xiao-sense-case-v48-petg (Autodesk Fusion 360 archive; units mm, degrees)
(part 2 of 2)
sketch "Sketch17" plane through (0, 15.93, 0) normal (0, 1, 0) x axis (-1, 0, 0)
  line L1 (6.08, -0.7317) -> (6.08, 1.4923)
  line L2 (6.08, -18.0556) -> (6.08, -15.8317)
  line L3 (11.723, -18.0556) -> (6.08, -18.0556)
  line L4 (17.1014, -8.74) -> (11.723, -18.0556)
  line L5 (17.1014, -7.8234) -> (17.1014, -8.74)
  line L6 (11.723, 1.4923) -> (17.1014, -7.8234)
  line L7 (6.08, 1.4923) -> (11.723, 1.4923)
  line L8 (17.1014, 8.429) -> (17.1014, -7.8234)
  line L9 (-4.8786, -7.7146) -> (-4.8786, 8.429)
  line L10 (6.08, 1.4923) -> (6.08, -0.7317)
  line L11 (0.437, 1.4923) -> (6.08, 1.4923)
  line L12 (-4.8786, -7.7146) -> (0.437, 1.4923)
  line L13 (-4.8786, -8.8487) -> (-4.8786, -7.7146)
  line L14 (0.437, -18.0556) -> (-4.8786, -8.8487)
  line L15 (6.08, -18.0556) -> (0.437, -18.0556)
  line L16 (6.08, -15.8317) -> (6.08, -18.0556)
  line L17 (17.1014, 43.4723) -> (17.1014, 8.429)
  line L18 (-4.8786, 43.4723) -> (17.1014, 43.4723)
  line L19 (-4.8786, 8.429) -> (-4.8786, 43.4723)
  line L20 (17.1014, 1.4923) -> (11.723, 1.4923)
  line L21 (10.58, -7.4067) -> (13.5791, -7.4067)
  line L22 (10.58, -9.1567) -> (10.58, -7.4067)
  line L23 (13.5791, -9.1567) -> (10.58, -9.1567)
  line L24 (1.58, -9.1567) -> (-1.4191, -9.1567)
  line L25 (1.58, -7.4067) -> (1.58, -9.1567)
  line L26 (-1.4191, -7.4067) -> (1.58, -7.4067)
  arc A1 centre (6.08, -8.2817) radius 7.55 clockwise from (6.08, -0.7317) to (13.5791, -7.4067)
  arc A2 centre (6.08, -8.2817) radius 7.55 clockwise from (6.08, -15.8317) to (-1.4191, -9.1567)
  arc A3 centre (6.08, -8.2817) radius 7.55 clockwise from (13.5791, -9.1567) to (6.08, -15.8317)
  arc A4 centre (6.08, -8.2817) radius 7.55 clockwise from (-1.4191, -7.4067) to (6.08, -0.7317)
  point P12 (17.1014, 8.429)
  point P24 (17.1014, 8.429)
  point P13 (-4.8786, 8.429)
  point P27 (-4.8786, 8.429)
  point P10 (11.723, 1.4923)
  point P28 (11.723, 1.4923)
  point P29 (17.1014, 1.4923)
  point P25 (17.1014, 43.4723)
  point P26 (-4.8786, 43.4723)
  coincident P12 P24
  parallel L8 L17
  perpendicular L17 L18
  perpendicular L18 L19
  coincident P13 P27
  coincident P10 P28
  coincident L8 P29
  perpendicular L8 L20
  dimension "d183" distance L7 L18 = 41.98 (= "AntennaLength + d280 - AntennaWidth")
  dimension "d280" distance P25 P26 = 21.98
extrude "Extrude41" add sketch "Sketch17" profile of L6 L8 L20 no distance stored
extrude "Extrude42" add sketch "Sketch17" profile of L7 L8 L9 L11 L12 L17 L18 L19 L20 no distance stored
sketch "Sketch18" plane through (-6.08, 0, 0) normal (1, 0, 0) x axis (0, 1, 0)
  line L1 (13.554, -18.0556) -> (9.88, -14.3817)
  line L2 (9.88, -14.3817) -> (8.5, -14.3817)
  line L3 (8.15, -12.7817) -> (8.15, -14.3817)
  line L4 (8.15, -14.3817) -> (8.5, -14.3817)
  line L5 (8.28, -12.7817) -> (9.88, -14.3817)
  line L6 (8.15, -12.7817) -> (8.28, -12.7817)
  line L7 (8.5, -14.3817) -> (8.5, -12.7817)
  line L8 (8.28, -12.7817) -> (8.5, -12.7817)
  point P4 (8.5, -14.3817)
  point P9 (8.5, -14.3817)
  point P6 (8.15, -14.3817)
  point P10 (8.15, -14.3817)
  point P5 (9.88, -14.3817)
  point P11 (9.88, -14.3817)
  point P8 (8.28, -12.7817)
  point P12 (8.28, -12.7817)
  point P7 (8.15, -12.7817)
  point P13 (8.15, -12.7817)
  point P14 (8.5, -12.7817)
  point P15 (8.5, -12.7817)
  coincident P4 P9
  coincident P6 P10
  coincident P5 P11
  coincident P8 P12
  coincident P7 P13
  coincident P14 P15
extrude "Extrude43" cut sketch "Sketch18" profile of L2 L3 L4 L5 L6 L7 to an object Side2Offset 0
extrude "Extrude44" add sketch "Sketch18" profile of L5 L7 L8 to an object
extrude "Extrude45" add sketch "Sketch18" profile of L5 L7 L8 to an object
sketch "Sketch19" plane through (0, 8.28, 0) normal (0, -1, 0) x axis (1, 0, 0)
  line L1 (-6.08, 0.6923) -> (-6.08, 9.4733)
  line L2 (-2.58, 0.6923) -> (-6.08, 0.6923)
  line L3 (-2.58, -3.7817) -> (-2.58, 0.6923)
  line L4 (-10.57, -3.7817) -> (-2.58, -3.7817)
  line L5 (-10.57, -12.7817) -> (-10.57, -3.7817)
  line L6 (-6.08, -12.7817) -> (-10.57, -12.7817)
  line L7 (-0.5867, -12.7817) -> (-6.08, -12.7817)
  line L8 (0.8736, -12.7817) -> (-0.5867, -12.7817)
  line L9 (3.2786, 6.6413) -> (3.2786, -10.3767)
  line L10 (-6.08, 9.4733) -> (0.2786, 9.4733)
  line L11 (-10.58, -3.7817) -> (-10.58, -12.7817)
  line L12 (-9.58, -3.7817) -> (-10.58, -3.7817)
  line L13 (-9.58, 0.6923) -> (-9.58, -3.7817)
  line L14 (-6.08, 0.6923) -> (-9.58, 0.6923)
  line L15 (-6.08, 9.4733) -> (-6.08, 0.6923)
  line L16 (-12.5014, 9.4733) -> (-6.08, 9.4733)
  line L17 (-15.5014, -10.3767) -> (-15.5014, 6.6413)
  line L18 (-12.2667, -12.7817) -> (-13.0964, -12.7817)
  line L19 (-10.58, -12.7817) -> (-12.2667, -12.7817)
  line L20 (1.4203, 2.8431) -> (-13.5797, 2.8431)
  line L21 (3.2786, 2.8431) -> (1.4203, 2.8431)
  line L22 (-15.5014, 2.8431) -> (-13.5797, 2.8431)
  arc A1 centre (0.8736, -10.3766) radius 2.405 clockwise from (3.2786, -10.3767) to (0.8736, -12.7817)
  closed curve K1 centre (0.2786, 6.6413)
  arc A2 centre (-12.6647, 6.6413) radius 2.8367 clockwise from (-15.5014, 6.6413) to (-12.5014, 9.4733)
  arc A3 centre (-13.0964, -10.3766) radius 2.405 clockwise from (-13.0964, -12.7817) to (-15.5014, -10.3767)
  point P30 (1.4203, 2.8431)
  point P31 (1.4203, 2.8431)
  point P32 (3.2786, 2.8431)
  point P29 (-13.5797, 2.8431)
  point P33 (-13.5797, 2.8431)
  point P34 (-15.5014, 2.8431)
  coincident P30 P31
  coincident L9 P32
  perpendicular L9 L21
  coincident P29 P33
  coincident L17 P34
  perpendicular L17 L22
extrude "Extrude46" add sketch "Sketch19" profile of L1 L15 L16 A2 L17 L20 L22 to an object offset 0.25 (= "Clearance")
extrude "Extrude47" add sketch "Sketch19" profile of L1 L9 K1 L10 L15 L20 L21 to an object offset 0.25 (= "Clearance")
split "Split1"
sketch "Sketch24" plane through (-6.08, 0, 0) normal (-1, 0, 0) x axis (0, -1, 0)
  line L1 (-4.1125, 11.0733) -> (-4.1125, 9.4733)
  line L2 (-9.08, 11.0733) -> (-4.1125, 11.0733)
  line L3 (-9.88, 10.2733) -> (-9.08, 11.0733)
  line L4 (-9.88, 1.4923) -> (-9.88, 10.2733)
  line L5 (-13.58, 1.4923) -> (-9.88, 1.4923)
  line L6 (-15.18, 1.4923) -> (-13.58, 1.4923)
  line L7 (-15.93, -0.7317) -> (-15.93, 1.4923)
  line L8 (-13.68, -0.7317) -> (-15.93, -0.7317)
  line L9 (-13.68, -4.4817) -> (-13.68, -0.7317)
  line L10 (-11.48, -3.7817) -> (-12.88, -3.7817)
  line L11 (-10.68, -2.9817) -> (-11.48, -3.7817)
  line L12 (-10.68, -0.1077) -> (-10.68, -2.9817)
  line L13 (-9.08, -0.1077) -> (-10.68, -0.1077)
  line L14 (-8.28, 0.6923) -> (-9.08, -0.1077)
  line L15 (-8.28, 2.8431) -> (-8.28, 0.6923)
  line L16 (-7.43, 2.8431) -> (-8.28, 2.8431)
  line L17 (-7.43, 9.4733) -> (-7.43, 2.8431)
  line L18 (-4.1125, 9.4733) -> (-7.43, 9.4733)
  line L19 (-2.2825, 9.4733) -> (-2.2825, 11.0733)
  line L20 (0.75, 9.4733) -> (-2.2825, 9.4733)
  line L21 (0.75, 7.1293) -> (0.75, 9.4733)
  line L22 (2.35, 7.1293) -> (0.75, 7.1293)
  line L23 (2.35, 10.2733) -> (2.35, 7.1293)
  line L24 (1.55, 11.0733) -> (2.35, 10.2733)
  line L25 (-2.2825, 11.0733) -> (1.55, 11.0733)
  line L26 (0.75, -12.7817) -> (0.75, -7.6707)
  line L27 (-0.75, -12.7817) -> (0.75, -12.7817)
  line L28 (-0.75, -14.3817) -> (-0.75, -12.7817)
  line L29 (1.55, -14.3817) -> (-0.75, -14.3817)
  line L30 (2.35, -13.5817) -> (1.55, -14.3817)
  line L31 (2.35, -7.6707) -> (2.35, -13.5817)
  line L32 (0.75, -7.6707) -> (2.35, -7.6707)
  line L33 (-8.28, -12.7817) -> (-13.554, -18.0556)
  line L34 (-9.88, -12.7817) -> (-8.28, -12.7817)
  line L35 (-12.88, -12.7817) -> (-9.88, -12.7817)
  line L36 (-13.68, -15.8317) -> (-13.68, -12.0817)
  line L37 (-15.93, -15.8317) -> (-13.68, -15.8317)
  line L38 (-15.93, -18.0556) -> (-15.93, -15.8317)
  line L39 (-13.554, -18.0556) -> (-15.93, -18.0556)
  line L40 (-14.805, 0.3803) -> (-14.805, -0.7317)
  line L41 (-14.805, 0.3803) -> (-15.93, 0.3803)
  line L42 (-14.81, 0.3853) -> (-14.81, -0.7317)
  line L43 (-10.68, 0.3853) -> (-14.81, 0.3853)
  line L44 (-14.8, 0.3753) -> (-14.8, -0.7317)
  line L45 (-10.68, 0.3753) -> (-14.8, 0.3753)
  line L46 (-14.805, -16.9436) -> (-15.93, -16.9436)
  line L47 (-14.81, -16.9486) -> (-14.81, -15.8317)
  line L48 (-12.447, -16.9486) -> (-14.81, -16.9486)
  line L49 (-14.8, -16.9386) -> (-14.8, -15.8317)
  line L50 (-12.437, -16.9386) -> (-14.8, -16.9386)
  line L51 (-10.68, 1.4923) -> (-10.68, -0.1077)
  line L52 (1.15, -13.5817) -> (-0.75, -13.5817)
  line L53 (1.55, -13.1817) -> (1.55, -7.6707)
  line L54 (1.55, -13.1817) -> (1.15, -13.5817)
  line L55 (0.75, -12.7817) -> (2.35, -13.5817)
  line L56 (1.555, -13.1837) -> (1.555, -7.6707)
  line L57 (1.555, -13.1837) -> (1.1521, -13.5867)
  line L58 (1.1521, -13.5867) -> (-0.75, -13.5867)
  line L59 (1.545, -13.1796) -> (1.545, -7.6707)
  line L60 (1.545, -13.1796) -> (1.1479, -13.5767)
  line L61 (1.1479, -13.5767) -> (-0.75, -13.5767)
  line L62 (0.75, 9.4733) -> (1.55, 11.0733)
  line L63 (1.55, 9.8733) -> (1.55, 7.1293)
  line L64 (1.15, 10.2733) -> (-2.2825, 10.2733)
  line L65 (1.55, 9.8733) -> (1.15, 10.2733)
  line L66 (1.545, 9.8713) -> (1.545, 7.1293)
  line L67 (1.545, 9.8713) -> (1.1479, 10.2683)
  line L68 (1.1479, 10.2683) -> (-2.2825, 10.2683)
  line L69 (1.555, 9.8754) -> (1.555, 7.1293)
  line L70 (1.555, 9.8754) -> (1.1521, 10.2783)
  line L71 (1.1521, 10.2783) -> (-2.2825, 10.2783)
  line L72 (-14.805, -16.9436) -> (-14.805, -15.8317)
  line L73 (-7.43, 7.1293) -> (0.75, 7.1293)
  line L74 (-9.88, 7.1293) -> (-7.43, 7.1293)
  line L75 (-8.655, 9.8733) -> (-8.655, 7.1293)
  line L76 (-8.255, 10.2733) -> (-4.1125, 10.2733)
  line L77 (-8.655, 9.8733) -> (-8.255, 10.2733)
  line L78 (-9.08, 11.0733) -> (-7.43, 9.4733)
  line L79 (-8.66, 9.8754) -> (-8.66, 7.1293)
  line L80 (-8.66, 9.8754) -> (-8.2571, 10.2783)
  line L81 (-8.2571, 10.2783) -> (-4.1125, 10.2783)
  line L82 (-8.2529, 10.2683) -> (-4.1125, 10.2683)
  line L83 (-8.65, 9.8713) -> (-8.2529, 10.2683)
  line L84 (-8.65, 9.8713) -> (-8.65, 7.1293)
  line L85 (-10.69, 1.4923) -> (-10.69, 0.3853)
  line L86 (-9.88, 7.1393) -> (-8.66, 7.1393)
  line L87 (-15.93, 1.4923) -> (-15.18, 1.4923)
  line L88 (-12.88, -4.4817) -> (-13.68, -4.4817)
  line L89 (-12.88, -3.7817) -> (-12.88, -4.4817)
  line L90 (-12.88, -12.0817) -> (-12.88, -12.7817)
  line L91 (-13.68, -12.0817) -> (-12.88, -12.0817)
  point P42 (-14.805, -0.7317)
  point P44 (-15.93, 0.3803)
  point P43 (-14.805, 0.3803)
  point P45 (-14.805, 0.3803)
  point P46 (-14.81, -0.7317)
  point P49 (-14.8, -0.7317)
  point P52 (-15.93, -16.9436)
  point P54 (-14.81, -15.8317)
  point P57 (-14.8, -15.8317)
  point P15 (-10.68, -0.1077)
  point P60 (-10.68, -0.1077)
  point P61 (-10.68, 1.4923)
  point P48 (-10.68, 0.3853)
  point P51 (-10.68, 0.3753)
  point P56 (-12.447, -16.9486)
  point P59 (-12.437, -16.9386)
  point P62 (-0.75, -13.5817)
  point P64 (1.55, -7.6707)
  point P63 (1.15, -13.5817)
  point P66 (1.15, -13.5817)
  point P65 (1.55, -13.1817)
  point P67 (1.55, -13.1817)
  point P33 (2.35, -13.5817)
  point P68 (2.35, -13.5817)
  point P29 (0.75, -12.7817)
  point P69 (0.75, -12.7817)
  point P27 (1.55, 11.0733)
  point P78 (1.55, 11.0733)
  point P23 (0.75, 9.4733)
  point P79 (0.75, 9.4733)
  point P80 (1.55, 7.1293)
  point P82 (-2.2825, 10.2733)
  point P84 (1.15, 10.2733)
  point P83 (1.15, 10.2733)
  point P81 (1.55, 9.8733)
  point P85 (1.55, 9.8733)
  point P94 (-14.805, -15.8317)
  point P53 (-14.805, -16.9436)
  point P95 (-14.805, -16.9436)
  point P24 (0.75, 7.1293)
  point P96 (0.75, 7.1293)
  point P97 (-7.43, 7.1293)
  point P98 (-9.88, 7.1293)
  point P99 (-8.655, 7.1293)
  point P101 (-4.1125, 10.2733)
  point P20 (-7.43, 9.4733)
  point P105 (-7.43, 9.4733)
  point P4 (-9.08, 11.0733)
  point P106 (-9.08, 11.0733)
  point P103 (-8.255, 10.2733)
  point P102 (-8.255, 10.2733)
  point P100 (-8.655, 9.8733)
  point P104 (-8.655, 9.8733)
  point P115 (-10.69, 0.3853)
  point P116 (-10.69, 1.4923)
  point P117 (-8.66, 7.1393)
  point P118 (-9.88, 7.1393)
  midpoint L8 P42
  perpendicular L8 L40
  midpoint L7 P44
  perpendicular L7 L41
  coincident P43 P45
  coincident L8 P46
  perpendicular L41 L42
  perpendicular L40 L43
  coincident L8 P49
  perpendicular L8 L44
  midpoint L38 P52
  perpendicular L38 L46
  coincident L37 P54
  perpendicular L46 L47
  coincident L37 P57
  perpendicular L37 L49
  coincident P15 P60
  coincident L5 P61
  perpendicular L5 L51
  coincident P48 L51
  coincident P51 L51
  coincident L33 P56
  coincident L33 P59
  midpoint L28 P62
  perpendicular L28 L52
  midpoint L32 P64
  perpendicular L32 L53
  parallel L30 L54
  coincident P63 P66
  coincident P65 P67
  coincident P33 P68
  coincident P29 P69
  coincident P67 L55
  coincident P27 P78
  coincident P23 P79
  midpoint L22 P80
  perpendicular L22 L63
  midpoint L19 P82
  perpendicular L19 L64
  parallel L24 L65
  coincident L62 P84
  coincident P83 P84
  coincident P81 P85
  midpoint L37 P94
  perpendicular L37 L72
  coincident P53 P95
  coincident P24 P96
  coincident L17 P97
  perpendicular L17 L73
  coincident L4 P98
  perpendicular L4 L74
  midpoint L74 P99
  perpendicular L74 L75
  midpoint L1 P101
  perpendicular L1 L76
  parallel L3 L77
  coincident P20 P105
  coincident P4 P106
  coincident P103 L78
  coincident P102 P103
  coincident P100 P104
  coincident L43 P115
  coincident L5 P116
  perpendicular L5 L85
  coincident L79 P117
  coincident L4 P118
  perpendicular L4 L86
  dimension "d241" distance L40 L42 = 0.005 (= "ClearanceSmall / 2")
  dimension "d242" distance L40 L44 = 0.005 (= "ClearanceSmall / 2")
  dimension "d243" distance L41 L45 = 0.005 (= "ClearanceSmall / 2")
  dimension "d245" distance L41 L43 = 0.005 (= "ClearanceSmall / 2")
  dimension "d246" distance L46 L48 = 0.005 (= "ClearanceSmall / 2")
  dimension "d247" distance L46 L50 = 0.005 (= "ClearanceSmall / 2")
  dimension "d250" = 0.005 (= "ClearanceSmall / 2")
  dimension "d251" = -0.005 (= "-ClearanceSmall / 2")
  dimension "d252" = 0.005 (= "ClearanceSmall / 2")
  dimension "d253" = -0.005 (= "-ClearanceSmall / 2")
  dimension "d254" distance L49 L72 = 0.005 (= "ClearanceSmall / 2")
  dimension "d255" distance L47 L72 = 0.005 (= "ClearanceSmall / 2")
  dimension "d256" = 0.005 (= "ClearanceSmall / 2")
  dimension "d257" = 0.005 (= "ClearanceSmall / 2")
  dimension "d266" distance L51 L85 = 0.01 (= "ClearanceSmall")
  dimension "d267" distance L74 L86 = 0.01 (= "ClearanceSmall")
extrude "Extrude54" add sketch "Sketch24" profile of L1 L2 L3 L4 L5 L6 L7 L8 L19 L22 L23 L24 L25 L28 L29 L30 L31 L32 L33 L37 L38 L39 L42 L43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 along normal blind 1.6 (= "WallThickness")
extrude "Extrude55" cut sketch "Sketch24" profile of L1 L2 L3 L4 L5 L6 L7 L8 L19 L22 L23 L24 L25 L28 L29 L30 L31 L32 L33 L37 L38 L39 L42 L43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 along normal blind 1.6 (= "WallThickness")
split "Split2" bodies "Left (1)", "Left (2)", "Left (3)", "Left (4)", "Left (5)"
split "Split3" bodies "Left (5) (1)", "Left (4) (1)"
combine "Combine1" bodies "Left (4) (1)", "Left (5) (1)"
combine "Combine2" bodies "Left (1)", "Left (2)", "Left (3)", "Left (4)", "Left (5)"
extrude "Extrude56" cut of existing geometry to an object
extrude "Extrude57" cut of existing geometry to an object
work_plane "WorkPlane6"
copy_paste_bodies "CopyPasteBodies1"
move "Move1" TranslateX 30 TranslateY 0 TranslateZ 0
copy_paste_bodies "CopyPasteBodies1"
move "Move1" TranslateX 0 TranslateY -0.5 TranslateZ 30
extrude "Extrude52" add of existing geometry to an object
extrude "Extrude53" add of existing geometry to an object
extrude "Extrude63" cut of existing geometry to an object
extrude "Extrude64" cut of existing geometry to an object
sketch "Sketch27" plane through (0, 13.68, 0) normal (0, 1, 0) x axis (-1, 0, 0)
  line L1 (-23.92, 0.3853) -> (-23.92, -4.4817)
  line L2 (-22.32, 0.3853) -> (-23.92, 0.3853)
  line L3 (-22.32, 1.4923) -> (-22.32, 0.3853)
  line L4 (-29.563, 1.4923) -> (-22.32, 1.4923)
  line L5 (-34.8786, -7.7146) -> (-29.563, 1.4923)
  line L6 (-34.8786, -8.8487) -> (-34.8786, -7.7146)
  line L7 (-29.563, -18.0556) -> (-34.8786, -8.8487)
  line L8 (-22.32, -16.9486) -> (-22.32, -18.0556)
  line L9 (-23.92, -16.9486) -> (-22.32, -16.9486)
  line L10 (-23.92, -12.0817) -> (-23.92, -16.9486)
  line L11 (-23.92, -16.9386) -> (-23.92, -12.0817)
  line L12 (-22.32, -16.9386) -> (-23.92, -16.9386)
  line L13 (-22.32, -18.0556) -> (-22.32, -16.9386)
  line L14 (-12.8986, -8.74) -> (-18.277, -18.0556)
  line L15 (-12.8986, -7.8234) -> (-12.8986, -8.74)
  line L16 (-18.277, 1.4923) -> (-12.8986, -7.8234)
  line L17 (-22.32, 1.4923) -> (-18.277, 1.4923)
  line L18 (-22.32, 0.3753) -> (-22.32, 1.4923)
  line L19 (-23.92, 0.3753) -> (-22.32, 0.3753)
  line L20 (-23.92, -4.4817) -> (-23.92, 0.3753)
  line L21 (-17.82, -2.1817) -> (-23.92, -2.1817)
  line L22 (-17.82, -14.3817) -> (-17.82, -2.1817)
  line L23 (-23.92, -14.3817) -> (-17.82, -14.3817)
  line L24 (-30.02, -14.3817) -> (-23.92, -14.3817)
  line L25 (-30.02, -2.1817) -> (-30.02, -14.3817)
  line L26 (-23.92, -2.1817) -> (-30.02, -2.1817)
  line L27 (-23.92, -2.9817) -> (-23.92, -0.1077)
  line L28 (-27.42, -2.9817) -> (-23.92, -2.9817)
  line L29 (-27.42, -0.1077) -> (-27.42, -2.9817)
  line L30 (-23.92, -0.1077) -> (-27.42, -0.1077)
  line L31 (-20.42, -0.1077) -> (-23.92, -0.1077)
  line L32 (-20.42, -2.9817) -> (-20.42, -0.1077)
  line L33 (-23.92, -2.9817) -> (-20.42, -2.9817)
  line L34 (-23.92, -0.1077) -> (-23.92, -2.9817)
  line L35 (-29.02, 1.4923) -> (-29.02, -2.9817)
  line L36 (-23.92, 1.4923) -> (-29.02, 1.4923)
  line L37 (-18.82, 1.4923) -> (-23.92, 1.4923)
  line L38 (-18.82, -2.9817) -> (-18.82, 1.4923)
  line L39 (-23.92, -12.0817) -> (-23.92, -4.4817)
  line L40 (-22.32, -18.0556) -> (-29.563, -18.0556)
  line L41 (-18.277, -18.0556) -> (-22.32, -18.0556)
  circle C1 centre (-23.92, -8.2817) radius 3.8
  arc A1 centre (-23.92, -8.2817) radius 3.8 clockwise from (-23.92, -12.0817) to (-23.92, -4.4817)
  arc A2 centre (-23.92, -8.2817) radius 3.8 clockwise from (-23.92, -4.4817) to (-23.92, -12.0817)
  point P25 (-23.92, -4.4817)
  point P45 (-23.92, -4.4817)
  point P14 (-23.92, -12.0817)
  point P46 (-23.92, -12.0817)
  point P47 (-23.92, -8.2817)
  coincident P25 P45
  coincident P14 P46
  midpoint L39 P47
  dimension "d294" diameter C1 = 7.6 (= "CameraRingDiameter + ClearanceBig")
extrude "Extrude65" cut sketch "Sketch27" profile of L1 L10 L11 L20 L21 L22 L23 L25 L24 L26 L27 L28 L29 L32 L33 L34 to an object offset 3
extrude "Extrude66" cut sketch "Sketch27" profile of L1 L2 L3 L4 L17 L18 L19 L20 L21 L26 L27 L29 L30 L31 L32 L34 L35 L38 L37 L36 no distance stored
extrude "Extrude67" sketch "Sketch27" profile of L1 L10 L11 L20 L21 L22 L23 L25 L24 L26 L27 L28 L29 L32 L33 L34 C1 blind 1.6 (= "WallThickness")
extrude "Extrude82" of existing geometry blind 3
extrude "Extrude68" cut sketch "Sketch27" profile of L8 L10 L11 L12 L13 L14 L15 L16 L17 L21 L22 L23 L38 to an object
extrude "Extrude69" cut of existing geometry to an object
extrude "Extrude70" cut of existing geometry to an object
extrude "Extrude71" add of existing geometry to an object
sketch "Sketch28" plane through (0, 9.88, 0) normal (0, 1, 0) x axis (-1, 0, 0)
  line L1 (-31.6842, -14.3817) -> (-34.0786, -11.9872)
  line L2 (-30.8736, -14.3817) -> (-31.6842, -14.3817)
  line L3 (-30.02, -14.3817) -> (-30.8736, -14.3817)
  line L4 (-30.02, -2.1817) -> (-30.02, -14.3817)
  line L5 (-29.02, -2.1817) -> (-30.02, -2.1817)
  line L6 (-29.02, 1.4923) -> (-29.02, -2.1817)
  line L7 (-23.92, 1.4923) -> (-29.02, 1.4923)
  line L8 (-23.92, 7.1393) -> (-23.92, 1.4923)
  line L9 (-22.32, 7.1393) -> (-23.92, 7.1393)
  line L10 (-22.32, 10.2733) -> (-22.32, 7.1393)
  line L11 (-31.9029, 10.2733) -> (-22.32, 10.2733)
  line L12 (-34.0786, 8.0977) -> (-31.9029, 10.2733)
  line L13 (-34.0786, -6.3289) -> (-34.0786, 8.0977)
  line L14 (-34.8786, -7.7146) -> (-34.0786, -6.3289)
  line L15 (-34.8786, -8.8487) -> (-34.8786, -7.7146)
  line L16 (-34.0786, -10.2344) -> (-34.8786, -8.8487)
  line L17 (-34.0786, -11.9872) -> (-34.0786, -10.2344)
  line L18 (-22.32, 7.1293) -> (-22.32, 10.2733)
  line L19 (-23.92, 7.1293) -> (-22.32, 7.1293)
  line L20 (-23.92, 1.4923) -> (-23.92, 7.1293)
  line L21 (-18.82, 1.4923) -> (-23.92, 1.4923)
  line L22 (-18.82, -2.1817) -> (-18.82, 1.4923)
  line L23 (-17.82, -2.1817) -> (-18.82, -2.1817)
  line L24 (-17.82, -14.3817) -> (-17.82, -2.1817)
  line L25 (-17.7333, -14.3817) -> (-17.82, -14.3817)
  line L26 (-16.1558, -14.3817) -> (-17.7333, -14.3817)
  line L27 (-13.6986, -11.9244) -> (-16.1558, -14.3817)
  line L28 (-13.6986, -10.1256) -> (-13.6986, -11.9244)
  line L29 (-12.8986, -8.74) -> (-13.6986, -10.1256)
  line L30 (-12.8986, -7.8234) -> (-12.8986, -8.74)
  line L31 (-13.6986, -6.4377) -> (-12.8986, -7.8234)
  line L32 (-13.6986, 8.0977) -> (-13.6986, -6.4377)
  line L33 (-15.8743, 10.2733) -> (-13.6986, 8.0977)
  line L34 (-22.32, 10.2733) -> (-15.8743, 10.2733)
  line L35 (-32.5325, -14.3817) -> (-31.6842, -14.3817)
  line L36 (-34.8786, -12.0356) -> (-32.5325, -14.3817)
  line L37 (-34.8786, -12.0356) -> (-34.8786, -8.8487)
  line L38 (-34.8786, -7.7146) -> (-34.8786, 8.429)
  line L39 (-34.8786, 8.429) -> (-32.2343, 11.0733)
  line L40 (-32.2343, 11.0733) -> (-22.32, 11.0733)
  line L41 (-22.32, 11.0733) -> (-15.5429, 11.0733)
  line L42 (-15.5429, 11.0733) -> (-12.8986, 8.429)
  line L43 (-12.8986, 8.429) -> (-12.8986, -7.8234)
  line L44 (-12.8986, -8.74) -> (-12.8986, -12.0356)
  line L45 (-15.2447, -14.3817) -> (-12.8986, -12.0356)
  line L46 (-16.1558, -14.3817) -> (-15.2447, -14.3817)
  line L47 (-22.32, 10.2733) -> (-22.32, 11.0733)
  point P43 (-22.32, 11.0733)
  point P52 (-22.32, 11.0733)
  point P19 (-22.32, 10.2733)
  point P53 (-22.32, 10.2733)
  coincident P43 P52
  coincident P19 P53
extrude "Extrude72" add sketch "Sketch28" profile of L27 L28 L29 L31 L32 L33 L34 L41 L42 L43 L44 L45 L46 L47 against normal blind 0.8 (magnitude of "-WallThickness / 2")
extrude "Extrude73" add sketch "Sketch28" profile of L1 L11 L12 L13 L14 L16 L17 L35 L36 L37 L38 L39 L40 L47 against normal blind 0.8 (magnitude of "-WallThickness / 2")
sketch "Sketch29" plane through (0, 0, -14.3817) normal (0, 0, -1) x axis (1, 0, 0)
  line L1 (17.7333, -9.88) -> (15.2447, -9.88)
  line L2 (17.7333, -6.7) -> (17.7333, -9.88)
  line L3 (23.92, -6.35) -> (18.0833, -6.35)
  line L4 (23.92, -4.46) -> (23.92, -6.35)
  line L5 (20.6613, -4.46) -> (23.92, -4.46)
  line L6 (19.1613, -2.25) -> (19.1613, -2.96)
  line L7 (22.32, -0.75) -> (20.6613, -0.75)
  line L8 (22.32, 1.55) -> (22.32, -0.75)
  line L9 (15.2447, 1.55) -> (22.32, 1.55)
  line L10 (15.2447, -9.88) -> (15.2447, 1.55)
  line L11 (29.4133, -9.88) -> (29.4133, -6.7)
  line L12 (23.92, -9.88) -> (29.4133, -9.88)
  line L13 (23.92, -12.88) -> (23.92, -9.88)
  line L14 (17.82, -15.88) -> (17.82, -12.88)
  line L15 (30.02, -9.88) -> (30.02, -15.88)
  line L16 (30.8736, -9.88) -> (30.02, -9.88)
  line L17 (30.8736, 1.55) -> (30.8736, -9.88)
  line L18 (22.32, 1.55) -> (30.8736, 1.55)
  line L19 (22.32, -0.75) -> (22.32, 1.55)
  line L20 (27.1013, -0.75) -> (22.32, -0.75)
  line L21 (28.6013, -2.96) -> (28.6013, -2.25)
  line L22 (23.92, -4.46) -> (27.1013, -4.46)
  line L23 (23.92, -6.35) -> (23.92, -4.46)
  line L24 (29.0633, -6.35) -> (23.92, -6.35)
  line L25 (23.92, -8.28) -> (29.4133, -8.28)
  line L26 (19.42, -8.28) -> (23.92, -8.28)
  line L27 (17.7333, -8.28) -> (19.42, -8.28)
  line L28 (23.92, -8.28) -> (23.92, -6.35)
  line L29 (29.4133, -7.315) -> (23.92, -7.315)
  line L30 (17.7333, -9.88) -> (23.92, -9.88)
  line L31 (23.92, -9.88) -> (23.92, -8.28)
  line L32 (30.02, -15.88) -> (17.82, -15.88)
  line L33 (17.82, -12.88) -> (23.92, -12.88)
  arc A1 centre (18.0833, -6.7) radius 0.35 clockwise from (17.7333, -6.7) to (18.0833, -6.35)
  arc A2 centre (20.6613, -2.96) radius 1.5 clockwise from (20.6613, -4.46) to (19.1613, -2.96)
  arc A3 centre (20.6613, -2.25) radius 1.5 clockwise from (19.1613, -2.25) to (20.6613, -0.75)
  arc A4 centre (27.1013, -2.25) radius 1.5 clockwise from (27.1013, -0.75) to (28.6013, -2.25)
  arc A5 centre (27.1013, -2.96) radius 1.5 clockwise from (28.6013, -2.96) to (27.1013, -4.46)
  arc A6 centre (29.0633, -6.7) radius 0.35 clockwise from (29.0633, -6.35) to (29.4133, -6.7)
  arc A7 centre (18.0833, -7.93) radius 0.35 clockwise from (18.0833, -8.28) to (17.7333, -7.93)
  arc A8 centre (29.0633, -7.93) radius 0.35 clockwise from (29.4133, -7.93) to (29.0633, -8.28)
  point P37 (23.92, -6.35)
  point P45 (23.92, -6.35)
  point P41 (23.92, -8.28)
  point P46 (23.92, -8.28)
  point P47 (23.92, -7.315)
  point P48 (29.4133, -7.315)
  point P4 (17.7333, -6.7)
  point P51 (17.7333, -7.93)
  point P5 (18.0833, -6.35)
  point P50 (18.0833, -8.28)
  point P18 (29.4133, -6.7)
  point P53 (29.4133, -7.93)
  point P38 (29.0633, -6.35)
  point P54 (29.0633, -8.28)
  point P20 (23.92, -9.88)
  point P55 (23.92, -9.88)
  point P3 (17.7333, -9.88)
  point P56 (17.7333, -9.88)
  point P42 (23.92, -8.28)
  point P57 (23.92, -8.28)
  point P58 (23.92, -9.88)
  coincident P37 P45
  coincident P41 P46
  midpoint L28 P47
  coincident L11 P48
  perpendicular L11 L29
  symmetric P4 L29 P51
  symmetric P5 L29 P50
  symmetric A1 L29 A7
  symmetric P18 L29 P53
  symmetric P38 L29 P54
  symmetric A6 L29 A8
  coincident P20 P55
  coincident P3 P56
  coincident P42 P57
  coincident P20 P58
extrude "Extrude74" add sketch "Sketch29" profile of L2 L26 L27 A7 L30 L31 to an object
extrude "Extrude75" add sketch "Sketch29" profile of L11 L12 L25 A8 L31 to an object
chamfer "Chamfer5" distance 0.8 (= "WallThickness / 2")
split "Split6" bodies "Right (1) (1)", "Right (1) (3)", "Right (1) (2)", "Right (1) (4)"
combine "Combine3" bodies "Right (1) (1)", "Right (1) (2)", "Right (1) (3)"
combine "Combine4" bodies "Right (1) (4)"
sketch "Sketch30" plane through (23.92, 0, 0) normal (-1, 0, 0) x axis (0, -1, 0)
  line L1 (-9.88, -12.7817) -> (-8.28, -12.7817)
  line L2 (-12.88, -12.7817) -> (-9.88, -12.7817)
  line L3 (-12.88, -12.0817) -> (-12.88, -12.7817)
  line L4 (-15.88, -12.0817) -> (-12.88, -12.0817)
  line L5 (-8.28, -14.3817) -> (-15.08, -14.3817)
  line L6 (-8.28, -12.7817) -> (-8.28, -14.3817)
  line L7 (-4.1125, 10.2783) -> (-4.1125, 9.4733)
  line L8 (-8.2571, 10.2783) -> (-4.1125, 10.2783)
  line L9 (-8.66, 9.8754) -> (-8.2571, 10.2783)
  line L10 (-8.66, 7.1393) -> (-8.66, 9.8754)
  line L11 (-9.88, 7.1393) -> (-8.66, 7.1393)
  line L12 (-9.88, 1.4923) -> (-9.88, 7.1393)
  line L13 (-11.48, 1.4923) -> (-9.88, 1.4923)
  line L14 (-12.28, 0.6923) -> (-11.48, 1.4923)
  line L15 (-12.28, -2.1817) -> (-12.28, 0.6923)
  line L16 (-15.08, -2.1817) -> (-12.28, -2.1817)
  line L17 (-12.88, -4.4817) -> (-15.88, -4.4817)
  line L18 (-12.88, -3.7817) -> (-12.88, -4.4817)
  line L19 (-11.48, -3.7817) -> (-12.88, -3.7817)
  line L20 (-10.68, -2.9817) -> (-11.48, -3.7817)
  line L21 (-10.68, -0.1077) -> (-10.68, -2.9817)
  line L22 (-9.08, -0.1077) -> (-10.68, -0.1077)
  line L23 (-8.28, 0.6923) -> (-9.08, -0.1077)
  line L24 (-8.28, 2.8431) -> (-8.28, 0.6923)
  line L25 (-7.43, 2.8431) -> (-8.28, 2.8431)
  line L26 (-7.43, 9.4733) -> (-7.43, 2.8431)
  line L27 (-4.1125, 9.4733) -> (-7.43, 9.4733)
  line L28 (-9.88, -14.3817) -> (-9.88, -12.7817)
  line L29 (-9.89, -14.3817) -> (-9.89, -12.7817)
  line L30 (-12.28, -3.7817) -> (-12.28, -2.1817)
  line L31 (-12.29, -3.7817) -> (-12.29, -2.1817)
  line L32 (-15.88, -13.5817) -> (-15.88, -12.0817)
  line L33 (-15.08, -14.3817) -> (-15.88, -13.5817)
  line L34 (-15.88, -2.9817) -> (-15.08, -2.1817)
  line L35 (-15.88, -4.4817) -> (-15.88, -2.9817)
  line L36 (-14.38, -13.1817) -> (-14.38, -12.0817)
  line L37 (-13.98, -13.5817) -> (-14.38, -13.1817)
  line L38 (-9.88, -13.5817) -> (-13.98, -13.5817)
  line L39 (-15.88, -13.5817) -> (-12.88, -12.7817)
  line L40 (-14.385, -13.1837) -> (-14.385, -12.0817)
  line L41 (-13.9821, -13.5867) -> (-14.385, -13.1837)
  line L42 (-9.88, -13.5867) -> (-13.9821, -13.5867)
  line L43 (-14.38, -3.3817) -> (-14.38, -4.4817)
  line L44 (-13.98, -2.9817) -> (-14.38, -3.3817)
  line L45 (-12.28, -2.9817) -> (-13.98, -2.9817)
  line L46 (-15.08, -2.1817) -> (-12.88, -3.7817)
  line L47 (-14.375, -3.3837) -> (-14.375, -4.4817)
  line L48 (-13.9779, -2.9867) -> (-14.375, -3.3837)
  line L49 (-12.28, -2.9867) -> (-13.9779, -2.9867)
  line L50 (-14.385, -3.3796) -> (-14.385, -4.4817)
  line L51 (-13.9821, -2.9767) -> (-14.385, -3.3796)
  line L52 (-12.28, -2.9767) -> (-13.9821, -2.9767)
  line L53 (-14.375, -13.1796) -> (-14.375, -12.0817)
  line L54 (-13.9779, -13.5767) -> (-14.375, -13.1796)
  line L55 (-9.88, -13.5767) -> (-13.9779, -13.5767)
  point P3 (-9.88, -12.7817)
  point P31 (-9.88, -12.7817)
  point P32 (-9.88, -14.3817)
  point P33 (-9.89, -12.7817)
  point P34 (-9.89, -14.3817)
  point P18 (-12.28, -2.1817)
  point P35 (-12.28, -2.1817)
  point P36 (-12.28, -3.7817)
  point P37 (-12.29, -2.1817)
  point P38 (-12.29, -3.7817)
  point P43 (-14.38, -12.0817)
  point P46 (-9.88, -13.5817)
  point P4 (-12.88, -12.7817)
  point P47 (-12.88, -12.7817)
  point P40 (-15.88, -13.5817)
  point P48 (-15.88, -13.5817)
  point P44 (-14.38, -13.1817)
  point P53 (-14.38, -4.4817)
  point P56 (-12.28, -2.9817)
  point P22 (-12.88, -3.7817)
  point P57 (-12.88, -3.7817)
  point P19 (-15.08, -2.1817)
  point P58 (-15.08, -2.1817)
  point P55 (-13.98, -2.9817)
  coincident P3 P31
  coincident L5 P32
  perpendicular L5 L28
  coincident L2 P33
  coincident L5 P34
  perpendicular L5 L29
  coincident P18 P35
  coincident L19 P36
  perpendicular L19 L30
  coincident L16 P37
  coincident L19 P38
  perpendicular L16 L31
  midpoint L4 P43
  perpendicular L4 L36
  perpendicular L36 L38
  midpoint L28 P46
  parallel L33 L37
  coincident P4 P47
  coincident P40 P48
  coincident P44 L39
  midpoint L17 P53
  perpendicular L17 L43
  parallel L17 L45
  midpoint L30 P56
  parallel L34 L44
  coincident P22 P57
  coincident P19 P58
  coincident P55 L46
  dimension "d318" distance L28 L29 = 0.01 (= "ClearanceSmall")
  dimension "d319" distance L30 L31 = 0.01 (= "ClearanceSmall")
  dimension "d348" = 0.005 (= "ClearanceSmall / 2")
  dimension "d349" = 0.005 (= "ClearanceSmall / 2")
  dimension "d350" = -0.005 (= "-ClearanceSmall / 2")
  dimension "d351" = -0.005 (= "-ClearanceSmall / 2")
extrude "Extrude76" add sketch "Sketch30" profile of L4 L5 L16 L17 L29 L31 L32 L33 L34 L35 L40 L42 L41 L50 L51 L52 along normal blind 1.6 (= "WallThickness")
extrude "Extrude77" cut sketch "Sketch30" profile of L4 L5 L16 L17 L28 L29 L30 L31 L32 L33 L34 L35 L40 L42 L41 L47 L48 L49 L50 L51 L52 L53 L55 L54 along normal blind 1.6 (= "WallThickness")
split "Split7" bodies "Right (Heatsink) (1)"
split "Split8" bodies "Left (1) (1) (2)", "Left (1) (1) (1)"
combine "Combine5" bodies "Left (1) (1) (1)", "Left (1) (1) (2)"
combine "Combine6" bodies "Right (Heatsink) (1)"
extrude "Extrude78" cut of existing geometry to an object
chamfer "Chamfer6" distance 0.8 (= "WallThickness / 2")
copy_paste_bodies "CopyPasteBodies2"
move "Move2" TranslateX 30 TranslateY 0 TranslateZ 0
extrude "Extrude79" add of existing geometry to an object
extrude "Extrude80" add of existing geometry to an object
extrude "Extrude81" cut of existing geometry to an object
move "Move3" TranslateX 0 TranslateY -0.5 TranslateZ 0
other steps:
base_feature "Base Feature1"
base_feature "Base Feature1" bodies "Left", "Right", "Right (Heatsink)", "Left (Heatsink)"
base_feature "Base Feature2" bodies "Right (1)", "Left (1)", "Left (Open)", "Right (Open)"
create_component "CreateComponent1"
create_component "CreateComponent1"
create_component "CreateComponent1"
create_component "CreateComponent1"
create_component "CreateComponent2"
create_component "CreateComponent3"
create_component "CreateComponent4"
create_component "CreateComponent5"
create_component "CreateComponent6"
create_component "CreateComponent7"
create_component "CreateComponent8"
create_component "CreateComponent9"
create_component "CreateComponent10"
create_component "CreateComponent11"
create_component "CreateComponent12"
create_component "CreateComponent13"
create_component "CreateComponent14"
create_component "CreateComponent15"
create_component "CreateComponent16"
create_component "CreateComponent17"
create_component "CreateComponent18"
create_component "CreateComponent19"
create_component "CreateComponent20"
create_component "CreateComponent21"
create_component "CreateComponent22"
create_component "CreateComponent23"
create_component "CreateComponent24"
create_component "CreateComponent2"
create_component "CreateComponent3"
create_component "CreateComponent1"
create_component "CreateComponent2"
create_component "CreateComponent4"
create_component "CreateComponent5"
create_component "CreateComponent2"
create_component "CreateComponent1"
create_component "CreateComponent2"
create_component "CreateComponent3"
create_component "CreateComponent4"
create_component "CreateComponent5"
create_component "CreateComponent3"
create_component "CreateComponent1"
extrude "Extrude1" cut sketch "Sketch18" profile of L2 L3 L4 L5 L6 L7 to an object Side2Offset 0
named bodies: "Right (Peephole)", "Left (Peephole)", "Left (1)", "Left (2)", "Left (3)", "Left (4)", "Left (5)", "Left (4) (1)", "Left (5) (1)", "Left", "Right", "Right (Heatsink)", "Left (Heatsink)", "Right (1) (1)", "Right (1) (2)", "Right (1) (3)", "Right (1) (4)", "Left (1) (1) (1)", "Left (1) (1) (2)", "Right (1)", "Left (Open)", "Right (Open)", "Right (Heatsink) (1)"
